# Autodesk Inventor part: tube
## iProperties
Shininess: 64.0
Length Units: 11269
Angle Units: 11279
Time Units: 11290
Mass Units: 11283
Length Display Precision: 3
Angle Display Precision: 2
Compacted: True
Part Number: tube
Document SubType Name: Modeling
Created: 2004-12
Material: Par défaut
Designer: LEGERET Philippe
Density: 0.0
Volumn: 0.0
Area: 0.0
PropertySet Name: Model Information
Control State: 0
Master: False
Checked Out: False
Author: LEGERET Philippe
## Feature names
1. Révolution1 [Revolution]
